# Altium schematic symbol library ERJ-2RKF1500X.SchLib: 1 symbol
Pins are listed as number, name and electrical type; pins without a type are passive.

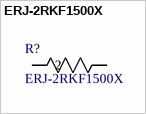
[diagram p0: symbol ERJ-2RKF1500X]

## ERJ-2RKF1500X
designator R?
Description; Manufacturer_Name: Panasonic
footprint RC0402N_PAN
pins: 1, 2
